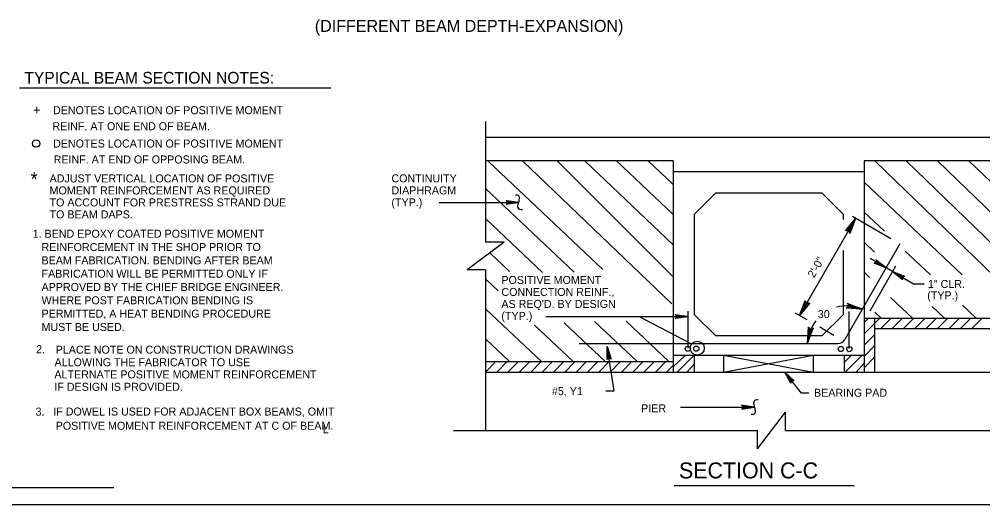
# Model space of a CAD drawing. Extents: x 641517 to 642372, y 298537 to 300319.
# Drawn here: x 641720.5 to 642081.6, y 299145.6 to 299327.8 of the extents above; entities that cross this region are included whole.
import ezdxf

# ---------------------------------------------------------------- set-up
doc = ezdxf.new("R2010")
doc.units = 0
for name, color, linetype in [('1', 7, 'Continuous'), ('2', 7, 'Continuous'), ('3', 7, 'Continuous'), ('4', 7, 'Continuous')]:
    doc.layers.add(name, color=color, linetype=linetype)

msp = doc.modelspace()

# ---------------------------------------------------------------- linework, layer by layer
at = {"layer": '1'}
for points in [[(641909.05, 299256.3), (641908.09, 299256.38), (641907.57, 299256.88), (641907.36, 299257.79), (641907.62, 299258.65), (641907.8, 299259.57), (641907.96, 299260.48), (641907.85, 299261.39), (641907.18, 299261.79), (641906.44, 299261.79)], [(641997.37, 299184.98), (641996.4, 299184.91), (641995.88, 299184.41), (641995.67, 299183.5), (641995.94, 299182.64), (641996.12, 299181.72), (641996.27, 299180.81), (641996.17, 299179.89), (641995.49, 299179.5), (641994.76, 299179.5)]]:
    msp.add_spline(points, degree=3, dxfattribs=at)
at = {"layer": '2'}
for p, q in [((641895.27, 299289.39), (641895.27, 299244.21)), ((641895.27, 299283.53), (642097.96, 299283.53)), ((641965.61, 299274.67), (641895.27, 299274.67)), ((641939.25, 299233.93), (641896.33, 299274.48)), ((641909.25, 299274.49), (641965.09, 299221.06)), ((641922.14, 299274.62), (641965.34, 299231.42)), ((641965.56, 299243.15), (641932.44, 299274.67)), ((641965.51, 299254.52), (641944.23, 299274.77)), ((641965.43, 299265.92), (641956.32, 299274.59)), ((641965.61, 299274.67), (641965.61, 299270.58)), ((641965.61, 299274.58), (641965.61, 299199.22)), ((642097.96, 299274.67), (642037.19, 299274.67)), ((642037.19, 299274.67), (642037.19, 299270.58)), ((642037.19, 299274.58), (642037.19, 299201.73)), ((642097.96, 299219.62), (642041.23, 299274.54)), ((642097.79, 299231.2), (642052.95, 299274.61)), ((642096.7, 299243.67), (642064.74, 299274.6)), ((642097.94, 299253.88), (642076.56, 299274.58)), ((642037.19, 299270.58), (641965.61, 299270.58)), ((642073.93, 299231.89), (642037.16, 299266.69)), ((641928.45, 299232.86), (641895.34, 299264.13)), ((641877.9, 299259.05), (641907.7, 299259.05)), ((642044.74, 299248.22), (642037.18, 299255.38)), ((641916.61, 299232.77), (641895.31, 299252.88)), ((642033.96, 299253.09), (642012.91, 299216.64)), ((642047.21, 299245.44), (642032.77, 299253.77)), ((641902.17, 299244.21), (641888.37, 299233.71)), ((641902.17, 299244.21), (641895.27, 299244.21)), ((642041.08, 299240.4), (642037.25, 299244.03)), ((642050.57, 299243.5), (642029.86, 299207.62)), ((642062, 299231.89), (642052.58, 299240.81)), ((641904.27, 299233.14), (641896.91, 299240.08)), ((642047.81, 299233.13), (642039.44, 299237.97)), ((641895.27, 299233.71), (641888.37, 299233.71)), ((641895.27, 299233.71), (641895.27, 299173.7)), ((642048.95, 299235.12), (642039.25, 299218.32)), ((642047.81, 299233.13), (642055.96, 299228.42)), ((641899.98, 299225.91), (641895.45, 299230.19)), ((642039.16, 299230.93), (642037.12, 299232.86)), ((642059.62, 299228.42), (642055.96, 299228.42)), ((642055.31, 299215.64), (642047.09, 299223.42)), ((641916.16, 299199.35), (641895.48, 299218.88)), ((642067.24, 299215.64), (642062.63, 299220)), ((642079.17, 299215.64), (642074.04, 299220.5)), ((641917.85, 299216.21), (641971.14, 299216.21)), ((641972.27, 299205.96), (641952.69, 299216.21)), ((641971.14, 299204.32), (641971.14, 299218.21)), ((642015.74, 299215), (642011.31, 299217.56)), ((642031.59, 299204.2), (642031.59, 299218.09)), ((642037.13, 299213.97), (642038.8, 299215.64)), ((642037.19, 299209.79), (642043.04, 299215.64)), ((642037.19, 299215.64), (642097.96, 299215.64)), ((642041.09, 299215.64), (642041.09, 299195.43)), ((642043.58, 299215.64), (642041.18, 299217.92)), ((642043.39, 299211.74), (642047.29, 299215.64)), ((642047.63, 299211.74), (642051.53, 299215.64)), ((642051.98, 299211.85), (642055.77, 299215.64)), ((642056.12, 299211.74), (642060.02, 299215.64)), ((642060.36, 299211.74), (642064.26, 299215.64)), ((642064.6, 299211.74), (642068.5, 299215.64)), ((642069.03, 299211.74), (642072.93, 299215.64)), ((642073.27, 299211.74), (642077.17, 299215.64)), ((642077.51, 299211.74), (642081.41, 299215.64)), ((641928.06, 299199.39), (641913.64, 299213.01)), ((641940.08, 299199.32), (641924.69, 299213.85)), ((641951.9, 299199.44), (641936.1, 299214.36)), ((641963.83, 299199.45), (641947.9, 299214.49)), ((642025.85, 299209.17), (642020.6, 299212.2)), ((642041.09, 299211.74), (642097.96, 299211.74)), ((641904.05, 299199.51), (641895.36, 299207.72)), ((642037.19, 299205.54), (642041.09, 299209.44)), ((641930.38, 299206.12), (642027.26, 299206.12)), ((641943.46, 299188.35), (641940.78, 299204.98)), ((642037.19, 299201.3), (642041.09, 299205.2)), ((641965.61, 299201.73), (642037.19, 299201.73)), ((641970.11, 299201.62), (641965.61, 299197.42)), ((641965.61, 299201.62), (641965.61, 299195.32)), ((641973.11, 299201.32), (641967.11, 299195.32)), ((641973.41, 299201.62), (641973.41, 299195.32)), ((641984.45, 299201.73), (641984.45, 299195.43)), ((641984.45, 299195.43), (642018.05, 299201.73)), ((641984.45, 299201.73), (642018.05, 299195.43)), ((642018.05, 299201.73), (642018.05, 299195.43)), ((642029.69, 299201.73), (642029.69, 299195.73)), ((642032.39, 299201.73), (642029.69, 299199.03)), ((642036.17, 299201.54), (642030.17, 299195.54)), ((642037.19, 299201.73), (642037.19, 299195.43)), ((642037.19, 299197.06), (642041.09, 299200.96)), ((641895.16, 299195.43), (641899.06, 299199.33)), ((641895.27, 299199.33), (641965.61, 299199.33)), ((641899.41, 299195.43), (641903.31, 299199.33)), ((641903.65, 299195.43), (641907.55, 299199.33)), ((641907.89, 299195.43), (641911.79, 299199.33)), ((641912.22, 299195.43), (641916.12, 299199.33)), ((641916.46, 299195.43), (641920.36, 299199.33)), ((641920.71, 299195.43), (641924.61, 299199.33)), ((641924.95, 299195.43), (641928.85, 299199.33)), ((641929.19, 299195.43), (641933.09, 299199.33)), ((641933.43, 299195.43), (641937.33, 299199.33)), ((641937.66, 299195.43), (641941.56, 299199.33)), ((641941.9, 299195.43), (641945.8, 299199.33)), ((641946.15, 299195.43), (641950.05, 299199.33)), ((641950.39, 299195.43), (641954.29, 299199.33)), ((641954.63, 299195.43), (641958.53, 299199.33)), ((641958.88, 299195.43), (641962.78, 299199.33)), ((641963.12, 299195.43), (641965.77, 299198.08)), ((641965.61, 299199.22), (641965.61, 299199.22)), ((641973.41, 299198.32), (641970.71, 299195.32)), ((641973.41, 299198.92), (641973.41, 299198.92)), ((641984.45, 299199.33), (641984.45, 299199.33)), ((642018.05, 299199.33), (642018.05, 299199.33)), ((642029.69, 299199.03), (642029.69, 299199.03)), ((642037.19, 299198.73), (642034.19, 299195.43)), ((642037.19, 299199.33), (642037.19, 299199.33)), ((641895.27, 299195.43), (642097.96, 299195.43)), ((642013.62, 299187.46), (642007.39, 299195.43)), ((641940.28, 299188.35), (641943.46, 299188.35)), ((642016.4, 299187.46), (642013.62, 299187.46)), ((641968.34, 299182.24), (641996.02, 299182.24)), ((641997.23, 299166.62), (642007.73, 299180.42)), ((642007.73, 299173.52), (642007.73, 299180.42)), ((641883.18, 299173.52), (641997.23, 299173.52)), ((641997.23, 299166.62), (641997.23, 299173.52)), ((642007.73, 299173.52), (642109.86, 299173.52)), ((641562.54, 299152.15), (641755.89, 299152.15)), ((642033.38, 299152.75), (641965.88, 299152.75)), ((642343.05, 299145.62), (641557.05, 299145.62))]:
    msp.add_line(p, q, dxfattribs=at)
for points in [[(642029.23, 299241.08), (642029.23, 299216.91), (642021.28, 299208.95), (641981.52, 299208.95), (641973.57, 299216.91), (641973.57, 299254.68), (641981.52, 299262.63), (642021.28, 299262.63), (642029.23, 299254.68), (642029.23, 299252.6)], [(642030.5, 299248.53), (642030.96, 299248.51), (642033.96, 299253.09), (642030.5, 299248.53), (642030.14, 299248.4), (642033.96, 299253.09), (642031.46, 299248.23), (642031.71, 299247.85), (642033.96, 299253.09), (642031.8, 299247.45), (642031.71, 299247.85)], [(642016.37, 299221.2), (642015.9, 299221.22), (642012.91, 299216.64), (642016.37, 299221.2), (642016.73, 299221.32), (642012.91, 299216.64), (642015.41, 299221.5), (642015.16, 299221.88), (642012.91, 299216.64), (642015.07, 299222.28), (642015.16, 299221.88)], [(642031.06, 299220.98), (642031.18, 299220.53), (642036.46, 299219.07), (642031.06, 299220.98), (642030.83, 299221.29), (642036.46, 299219.07), (642031.06, 299219.97), (642030.78, 299219.62), (642036.46, 299219.07), (642030.42, 299219.42), (642030.78, 299219.62)], [(642017.8, 299211.74), (642017.35, 299211.63), (642015.89, 299206.35), (642017.8, 299211.74), (642018.1, 299211.98), (642015.89, 299206.35), (642016.79, 299211.74), (642016.44, 299212.02), (642015.89, 299206.35), (642016.24, 299212.38), (642016.44, 299212.02)], [(641940.94, 299200.33), (641941.24, 299200.55), (641940.78, 299204.98), (641940.94, 299200.33), (641940.78, 299200.07), (641940.78, 299204.98), (641941.7, 299200.63), (641942.05, 299200.52), (641940.78, 299204.98), (641942.31, 299200.31), (641942.05, 299200.52)]]:
    msp.add_lwpolyline(points, dxfattribs=at)
for centre, radius in [((641971.03, 299204.17), 0.971), ((641974.59, 299204.37), 2.63), ((641974.23, 299204.19), 0.971), ((642028.42, 299204.07), 0.971), ((642031.59, 299204.03), 0.971)]:
    msp.add_circle(centre, radius, dxfattribs=at)
for centre, radius, start, end in [((642030.66, 299205.46), 14.79, 66.9296, 105.3369), ((642030.66, 299205.46), 14.79, 141.6259, 176.5318), ((642027.26, 299209.12), 3, 270, 330)]:
    msp.add_arc(centre, radius, start, end, dxfattribs=at)
at = {"layer": '3'}
msp.add_line((641720.51, 299302.08), (641837.3, 299302.08), dxfattribs=at)
for points in [[(641903.16, 299259.63), (641903.33, 299259.3), (641907.7, 299259.05), (641903.16, 299259.63), (641902.93, 299259.82), (641907.7, 299259.05), (641903.33, 299258.84), (641903.17, 299258.51), (641907.7, 299259.05), (641902.92, 299258.3), (641903.17, 299258.51)], [(642041.75, 299237.3), (642041.73, 299236.93), (642045.39, 299234.53), (642041.75, 299237.3), (642041.65, 299237.58), (642045.39, 299234.53), (642041.51, 299236.53), (642041.21, 299236.33), (642045.39, 299234.53), (642040.88, 299236.26), (642041.21, 299236.33)], [(642051.45, 299230.36), (642051.47, 299230.73), (642047.81, 299233.13), (642051.45, 299230.36), (642051.55, 299230.08), (642047.81, 299233.13), (642051.69, 299231.13), (642051.99, 299231.33), (642047.81, 299233.13), (642052.32, 299231.4), (642051.99, 299231.33)], [(641966.59, 299216.79), (641966.77, 299216.46), (641971.14, 299216.21), (641966.59, 299216.79), (641966.36, 299216.99), (641971.14, 299216.21), (641966.77, 299216), (641966.61, 299215.68), (641971.14, 299216.21), (641966.36, 299215.46), (641966.61, 299215.68)], [(642009.73, 299191.5), (642009.89, 299191.83), (642007.39, 299195.43), (642009.73, 299191.5), (642009.72, 299191.19), (642007.39, 299195.43), (642010.25, 299192.12), (642010.6, 299192.19), (642007.39, 299195.43), (642010.92, 299192.13), (642010.6, 299192.19)], [(641991.48, 299181.66), (641991.65, 299181.99), (641996.02, 299182.24), (641991.48, 299181.66), (641991.24, 299181.46), (641996.02, 299182.24), (641991.65, 299182.45), (641991.49, 299182.77), (641996.02, 299182.24), (641991.24, 299182.99), (641991.49, 299182.77)]]:
    msp.add_lwpolyline(points, dxfattribs=at)
at = {"layer": '4'}
msp.add_circle((641726.79, 299281.15), 1.4, dxfattribs=at)

# ---------------------------------------------------------------- texts
at = {"layer": '1'}
msp.add_text('TYPICAL BEAM SECTION NOTES:', height=4.375, dxfattribs=at).set_placement((641722.37, 299303.67))
at = {"layer": '2'}
for s, height, p in [('(DIFFERENT BEAM DEPTH-EXPANSION)', 4.5, (641831.23, 299323.05)), ('3.', 3, (641726.56, 299179.08)), ('SECTION C-C', 6, (641967.73, 299155.5))]:
    msp.add_text(s, height=height, dxfattribs=at).set_placement(p)
at = {"layer": '3'}
for s, height, p in [('DENOTES LOCATION OF POSITIVE MOMENT', 2.999, (641733.1, 299292.17)), ('REINF. AT ONE END OF BEAM.', 2.999, (641732.85, 299286.17)), ('DENOTES LOCATION OF POSITIVE MOMENT', 2.999, (641733.13, 299279.66)), ('REINF. AT END OF OPPOSING BEAM.', 2.999, (641733.34, 299273.68)), ('*', 5.18, (641724.67, 299265.24)), ('ADJUST VERTICAL LOCATION OF POSITIVE', 2.999, (641731.81, 299266.57)), ('CONTINUITY', 2.997, (641859.96, 299266.59)), ('MOMENT REINFORCEMENT AS REQUIRED', 2.999, (641731.81, 299262.07)), ('DIAPHRAGM', 2.997, (641859.96, 299262.09)), ('TO ACCOUNT FOR PRESTRESS STRAND DUE', 2.999, (641731.81, 299257.57)), ('(TYP.)', 2.997, (641859.96, 299257.59)), ('TO BEAM DAPS.', 2.999, (641731.81, 299253.07)), ('1. BEND EPOXY COATED POSITIVE MOMENT', 2.9979, (641725.46, 299245.82)), ('   REINFORCEMENT IN THE SHOP PRIOR TO ', 2.9979, (641725.46, 299240.82)), ('   BEAM FABRICATION. BENDING AFTER BEAM', 2.9979, (641725.46, 299235.82)), ('   FABRICATION WILL BE PERMITTED ONLY IF', 2.9979, (641725.46, 299230.83)), ('POSITIVE MOMENT', 2.9969, (641901.18, 299228.47)), ('   APPROVED BY THE CHIEF BRIDGE ENGINEER.', 2.9979, (641725.46, 299225.83)), ('CONNECTION REINF.,', 2.9969, (641901.18, 299223.97)), ('   WHERE POST FABRICATION BENDING IS', 2.9979, (641725.46, 299220.83)), ("AS REQ'D. BY DESIGN", 2.9969, (641901.18, 299219.48)), ('   PERMITTED, A HEAT BENDING PROCEDURE', 2.9979, (641725.46, 299215.83)), ('(TYP.)', 2.997, (641901.18, 299214.98)), ('   MUST BE USED.', 2.9979, (641725.46, 299210.83)), ('2.', 3, (641726.75, 299202.49)), ('PLACE NOTE ON CONSTRUCTION DRAWINGS', 3, (641734.11, 299202.32)), ('ALLOWING THE FABRICATOR TO USE', 3, (641733.68, 299197.6)), ('ALTERNATE POSITIVE MOMENT REINFORCEMENT', 3, (641733.61, 299193.03)), ('IF DESIGN IS PROVIDED.', 3, (641733.61, 299188.38)), ('#5, Y1', 2.997, (641920.11, 299186.75)), ('BEARING PAD', 2.9969, (642018.37, 299186.15)), ('PIER', 2.999, (641953.55, 299180.29)), ('IF DOWEL IS USED FOR ADJACENT BOX BEAMS, OMIT', 3, (641733.19, 299179.1)), ('POSITIVE MOMENT REINFORCEMENT AT C OF BEAM.', 3, (641734.1, 299173.77)), ('L', 3, (641834.19, 299172.48))]:
    msp.add_text(s, height=height, dxfattribs=at).set_placement(p)
for s, rotation, p in [('2\'-0"', 60, (642018.36, 299230.52)), ('1" CLR.', 360, (642061.05, 299226.96)), ('(TYP.)', 360, (642060.81, 299222.7)), ('30', 360, (642019.78, 299215.66))]:
    msp.add_text(s, height=2.997, rotation=rotation, dxfattribs=at).set_placement(p)
at = {"layer": '4'}
msp.add_text('+', height=3.6, dxfattribs=at).set_placement((641725.63, 299291.98))

doc.saveas('drawing.dxf')
